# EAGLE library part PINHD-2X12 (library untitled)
PIN HEADER
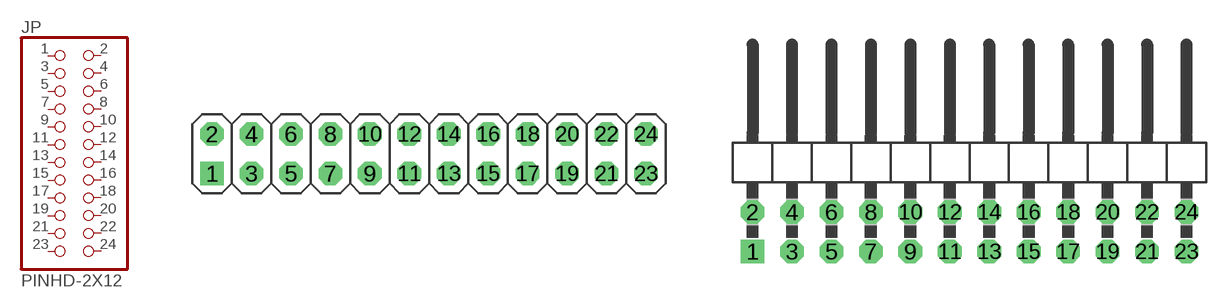
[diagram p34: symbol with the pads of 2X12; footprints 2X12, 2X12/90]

Designator prefix JP

## PINHD-2X12_2.54  [2X12]
1  1  pas
2  2  pas
3  3  pas
4  4  pas
5  5  pas
6  6  pas
7  7  pas
8  8  pas
9  9  pas
10  10  pas
11  11  pas
12  12  pas
13  13  pas
14  14  pas
15  15  pas
16  16  pas
17  17  pas
18  18  pas
19  19  pas
20  20  pas
21  21  pas
22  22  pas
23  23  pas
24  24  pas

## PINHD-2X12_2.54-90°  [2X12/90]
Pads as for 2X12

## PINHD-2X12_2.00  [2X12M]
Pads as for 2X12

## PINHD-2X12_2.54-SMD  [2X12SMD]
Pads as for 2X12

## PINHD-2X12_2.54-SMD-90°  [2X12SMD/90]
Pads as for 2X12

## Footprint 2X12 (pad centres in mm)
PIN HEADER - 2.54
drill 1.016 square: 1 -13.97,-1.27
drill 1.016 octagon: 2 -13.97,1.27; 3 -11.43,-1.27; 4 -11.43,1.27; 5 -8.89,-1.27; 6 -8.89,1.27; 7 -6.35,-1.27; 8 -6.35,1.27; 9 -3.81,-1.27; 10 -3.81,1.27; 11 -1.27,-1.27; 12 -1.27,1.27; 13 1.27,-1.27; 14 1.27,1.27; 15 3.81,-1.27; 16 3.81,1.27; 17 6.35,-1.27; 18 6.35,1.27; 19 8.89,-1.27; 20 8.89,1.27; 21 11.43,-1.27; 22 11.43,1.27; 23 13.97,-1.27; 24 13.97,1.27

## Footprint 2X12/90 (pad centres in mm)
PIN HEADER - 2.54 90°
drill 1.016 square: 1 -13.97,-6.35
drill 1.016 octagon: 2 -13.97,-3.81; 3 -11.43,-6.35; 4 -11.43,-3.81; 5 -8.89,-6.35; 6 -8.89,-3.81; 7 -6.35,-6.35; 8 -6.35,-3.81; 9 -3.81,-6.35; 10 -3.81,-3.81; 11 -1.27,-6.35; 12 -1.27,-3.81; 13 1.27,-6.35; 14 1.27,-3.81; 15 3.81,-6.35; 16 3.81,-3.81; 17 6.35,-6.35; 18 6.35,-3.81; 19 8.89,-6.35; 20 8.89,-3.81; 21 11.43,-6.35; 22 11.43,-3.81; 23 13.97,-6.35; 24 13.97,-3.81

## Footprint 2X12M (pad centres in mm)
PIN HEADER - 2
drill 0.914 square: 1 -11,-1
drill 0.914 round: 2 -11,1; 3 -9,-1; 4 -9,1; 5 -7,-1; 6 -7,1; 7 -5,-1; 8 -5,1; 9 -3,-1; 10 -3,1; 11 -1,-1; 12 -1,1; 13 1,-1; 14 1,1; 15 3,-1; 16 3,1; 17 5,-1; 18 5,1; 19 7,-1; 20 7,1; 21 9,-1; 22 9,1; 23 11,-1; 24 11,1

## Footprint 2X12SMD (pad centres in mm)
PIN HEADER - 2.54 SMD
smd 1.016 x 3.302: 1 -1.27,-3.81; 2 -1.27,1.27; 3 1.27,-3.81; 4 1.27,1.27; 5 3.81,-3.81; 6 3.81,1.27; 7 6.35,-3.81; 8 6.35,1.27; 9 8.89,-3.81; 10 8.89,1.27; 11 11.43,-3.81; 12 11.43,1.27; 13 13.97,-3.81; 14 13.97,1.27; 15 16.51,-3.81; 16 16.51,1.27; 17 19.05,-3.81; 18 19.05,1.27; 19 21.59,-3.81; 20 21.59,1.27; 21 24.13,-3.81; 22 24.13,1.27; 23 26.67,-3.81; 24 26.67,1.27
